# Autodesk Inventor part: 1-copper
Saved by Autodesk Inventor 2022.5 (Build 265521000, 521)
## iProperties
Created: 2025-02
Part Number: 1-copper
Material: Generic
Document SubType Name: Modeling
Designer: AdminForWorker
Density: 1 g/cm^3
Appearance: Default
Title: 1-copper
Author: AdminForWorker
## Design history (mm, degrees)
feature "Body1"
feature "Body3"
feature "Body2"
feature "Body4"
body "Solid1"
body "Solid2"
body "Solid3"
body "Solid4"
